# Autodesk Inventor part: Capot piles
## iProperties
Created: 2002-04
Part Number: Capot piles
Material: Par défaut
Document SubType Name: Modélisation
Designer: Flavien MARTY
Control State: 0
Master: False
Checked Out: False
Shininess: 20.0
Length Units: 11269
Angle Units: 11279
Time Units: 11290
Mass Units: 11283
Length Display Precision: 3
Angle Display Precision: 2
Compacted: True
Density: 0.0
Volumn: 0.0
Area: 0.0
PropertySet Name: Model Information
Author: Flavien MARTY
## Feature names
1. Extrusion1
2. Extrusion2
3. Extrusion3
4. Extrusion4
5. Congé1 [Fillet]
6. Chanfrein1 [Chamfer]
7. Extrusion5
8. Extrusion6
9. Extrusion7
10. Extrusion8
11. Réseau rectangulaire1 [Rectangular Pattern]
12. Extrusion9
13. Extrusion10
14. OPEN [Extrusion]
